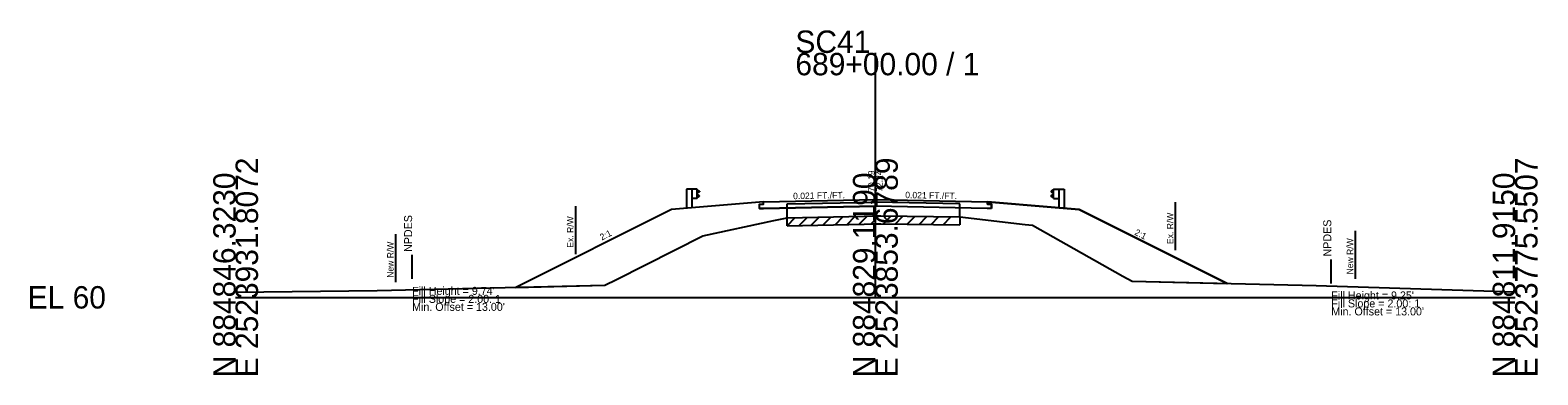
# Model space of a CAD drawing. Extents: x -26 to 183, y -10 to 24021.
# Drawn here: x -25.7 to 162.8, y 16490.3 to 16533.4 of the extents above; entities that cross this region are included whole.
import ezdxf

# ---------------------------------------------------------------- set-up
doc = ezdxf.new("R2010")
doc.units = 0
for name, color, linetype in [('RD_GPK_XS_Cell', 7, 'Continuous'), ('RD_XS_Base', 7, 'Continuous'), ('RD_XS_Buildup', 7, 'Continuous'), ('RD_XS_EarthShd', 7, 'Continuous'), ('RD_XS_EwShp', 7, 'Continuous'), ('RD_XS_ExGround', 7, 'Continuous'), ('RD_XS_ExPaveRet', 7, 'Continuous'), ('RD_XS_ExRW', 7, 'Continuous'), ('RD_XS_GR', 7, 'Continuous'), ('RD_XS_NewRW', 7, 'Continuous'), ('RD_XS_NPDES', 7, 'Continuous'), ('RD_XS_Pave', 7, 'Continuous'), ('RD_XS_TieSlope', 7, 'Continuous'), ('RD_XS_TX_Elev_EX', 7, 'Continuous'), ('RD_XS_TX_Elev_PR', 7, 'Continuous'), ('RD_XS_TX_Slope', 7, 'Continuous'), ('RD_XS_TX_Warning', 7, 'Continuous')]:
    doc.layers.add(name, color=color, linetype=linetype)

msp = doc.modelspace()

# ---------------------------------------------------------------- linework, layer by layer
at = {"layer": 'RD_GPK_XS_Cell'}
for p, q in [((80, 16500), (80, 16530.57)), ((0, 16500), (80, 16500)), ((80, 16500), (160, 16500))]:
    msp.add_line(p, q, dxfattribs=at)
at = {"layer": 'RD_XS_Base'}
for p in [(66.01, 16511.11), (93.99, 16511.11)]:
    msp.add_line(p, (80, 16511.4), dxfattribs=at)
at = {"layer": 'RD_XS_Buildup'}
for p, q in [((68.96, 16511.69), (80, 16511.92)), ((68.96, 16509.94), (68.96, 16511.69)), ((90.58, 16511.7), (80, 16511.92)), ((90.58, 16510.05), (90.58, 16511.7))]:
    msp.add_line(p, q, dxfattribs=at)
at = {"layer": 'RD_XS_EarthShd'}
for p, q in [((66, 16511.95), (58, 16511.28)), ((94, 16511.95), (102, 16511.28)), ((58, 16511.28), (54.5, 16510.99)), ((102, 16511.28), (105.5, 16510.99))]:
    msp.add_line(p, q, dxfattribs=at)
at = {"layer": 'RD_XS_EwShp'}
msp.add_lwpolyline([(94.5, 16511.1), (93.99, 16511.11), (80, 16511.4), (66.01, 16511.11), (65.5, 16511.1), (65.5, 16511.65), (66, 16511.66), (66, 16511.95), (58, 16511.28), (54.5, 16510.99), (35.02, 16501.25), (46.18, 16501.51), (47.64, 16502.25), (58.42, 16507.69), (67.29, 16509.59), (68.96, 16509.94), (78.58, 16510.16), (79.65, 16510.19), (80, 16510.19), (80.67, 16510.18), (90.58, 16510.05), (98.72, 16509.13), (99.65, 16509.01), (110.95, 16502.65), (112.09, 16502.01), (124.01, 16501.74), (105.5, 16510.99), (102, 16511.28), (94, 16511.95), (94, 16511.66), (94.5, 16511.65)], close=True, dxfattribs=at)
msp.add_lwpolyline([(94.5, 16511.1), (93.99, 16511.11), (80, 16511.4), (66.01, 16511.11), (65.5, 16511.1), (65.5, 16511.65), (66, 16511.66), (66, 16511.95), (58, 16511.28), (54.5, 16510.99), (35.02, 16501.25), (46.18, 16501.51), (47.64, 16502.25), (58.42, 16507.69), (67.29, 16509.59), (68.96, 16509.94), (78.58, 16510.16), (79.65, 16510.19), (80, 16510.19), (80.67, 16510.18), (90.58, 16510.05), (98.72, 16509.13), (99.65, 16509.01), (110.95, 16502.65), (112.09, 16502.01), (124.01, 16501.74), (105.5, 16510.99), (102, 16511.28), (94, 16511.95), (94, 16511.66), (94.5, 16511.65)], close=True, dxfattribs=at)
msp.add_lwpolyline([(94.5, 16511.1), (93.99, 16511.11), (80, 16511.4), (66.01, 16511.11), (65.5, 16511.1), (65.5, 16511.65), (66, 16511.66), (66, 16511.95), (58, 16511.28), (54.5, 16510.99), (35.02, 16501.25), (46.18, 16501.51), (47.64, 16502.25), (58.42, 16507.69), (67.29, 16509.59), (68.96, 16509.94), (78.58, 16510.16), (79.65, 16510.19), (80, 16510.19), (80.67, 16510.18), (90.58, 16510.05), (98.72, 16509.13), (99.65, 16509.01), (110.95, 16502.65), (112.09, 16502.01), (124.01, 16501.74), (105.5, 16510.99), (102, 16511.28), (94, 16511.95), (94, 16511.66), (94.5, 16511.65)], close=True, dxfattribs=at)
msp.add_lwpolyline([(94.5, 16511.1), (93.99, 16511.11), (80, 16511.4), (66.01, 16511.11), (65.5, 16511.1), (65.5, 16511.65), (66, 16511.66), (66, 16511.95), (58, 16511.28), (54.5, 16510.99), (35.02, 16501.25), (46.18, 16501.51), (47.64, 16502.25), (58.42, 16507.69), (67.29, 16509.59), (68.96, 16509.94), (78.58, 16510.16), (79.65, 16510.19), (80, 16510.19), (80.67, 16510.18), (90.58, 16510.05), (98.72, 16509.13), (99.65, 16509.01), (110.95, 16502.65), (112.09, 16502.01), (124.01, 16501.74), (105.5, 16510.99), (102, 16511.28), (94, 16511.95), (94, 16511.66), (94.5, 16511.65)], close=True, dxfattribs=at)
at = {"layer": 'RD_XS_ExGround'}
for p, q in [((67.29, 16509.59), (68.96, 16509.94)), ((68.96, 16509.94), (78.58, 16510.16)), ((78.58, 16510.16), (79.65, 16510.19)), ((79.65, 16510.19), (80, 16510.19)), ((80, 16510.19), (80.67, 16510.18)), ((80.67, 16510.18), (90.58, 16510.05)), ((90.58, 16510.05), (98.72, 16509.13)), ((58.42, 16507.69), (67.29, 16509.59)), ((98.72, 16509.13), (99.65, 16509.01)), ((99.65, 16509.01), (110.95, 16502.65)), ((47.64, 16502.25), (58.42, 16507.69)), ((110.95, 16502.65), (112.09, 16502.01)), ((0, 16500.64), (17.69, 16500.85)), ((17.69, 16500.85), (46.18, 16501.51)), ((46.18, 16501.51), (47.64, 16502.25)), ((112.09, 16502.01), (135.13, 16501.48)), ((135.13, 16501.48), (160, 16500.69))]:
    msp.add_line(p, q, dxfattribs=at)
at = {"layer": 'RD_XS_ExPaveRet'}
for p, q in [((68.96, 16508.94), (69.98, 16509.97)), ((68.96, 16508.94), (68.96, 16509.94)), ((70.46, 16508.98), (71.48, 16510)), ((71.96, 16509.01), (72.98, 16510.04)), ((73.46, 16509.05), (74.48, 16510.07)), ((74.96, 16509.08), (75.98, 16510.11)), ((76.46, 16509.12), (77.48, 16510.14)), ((77.96, 16509.15), (78.98, 16510.17)), ((79.46, 16509.19), (80.45, 16510.18)), ((80.96, 16509.17), (81.94, 16510.16)), ((82.46, 16509.16), (83.44, 16510.14)), ((83.96, 16509.14), (84.94, 16510.12)), ((85.46, 16509.12), (86.44, 16510.11)), ((86.96, 16509.1), (87.94, 16510.09)), ((88.46, 16509.08), (89.44, 16510.07)), ((90.58, 16510.05), (90.58, 16509.05)), ((68.96, 16508.94), (78.58, 16509.16)), ((78.58, 16509.16), (79.65, 16509.19)), ((79.65, 16509.19), (80, 16509.19)), ((80, 16509.19), (80.67, 16509.18)), ((80.67, 16509.18), (90.58, 16509.05))]:
    msp.add_line(p, q, dxfattribs=at)
at = {"layer": 'RD_XS_ExRW'}
for p, q in [((117.5, 16511.89), (117.5, 16505.89)), ((42.5, 16511.42), (42.5, 16505.42))]:
    msp.add_line(p, q, dxfattribs=at)
at = {"layer": 'RD_XS_GR'}
for p, q in [((56.4, 16513.53), (56.4, 16511.15)), ((57.06, 16513.53), (56.4, 16513.53)), ((57.06, 16513.53), (57.06, 16511.2)), ((57.73, 16513.53), (57.06, 16513.53)), ((57.73, 16512.36), (57.06, 16512.36)), ((57.73, 16512.36), (57.73, 16513.53)), ((57.73, 16513.46), (58, 16513.26)), ((58, 16513.21), (57.73, 16513.01)), ((58, 16512.69), (57.73, 16512.89)), ((57.73, 16512.44), (58, 16512.64)), ((58, 16513.26), (58, 16513.21)), ((58, 16512.64), (58, 16512.69)), ((102.27, 16513.46), (102, 16513.26)), ((102, 16513.26), (102, 16513.21)), ((102, 16513.21), (102.27, 16513.01)), ((102, 16512.69), (102.27, 16512.89)), ((102, 16512.64), (102, 16512.69)), ((102.27, 16512.44), (102, 16512.64)), ((102.27, 16512.36), (102.27, 16513.53)), ((102.27, 16513.53), (102.94, 16513.53)), ((102.27, 16512.36), (102.94, 16512.36)), ((102.94, 16513.53), (102.94, 16511.2)), ((102.94, 16513.53), (103.6, 16513.53)), ((103.6, 16513.53), (103.6, 16511.15))]:
    msp.add_line(p, q, dxfattribs=at)
at = {"layer": 'RD_XS_NewRW'}
for p, q in [((140, 16508.32), (140, 16502.32)), ((20, 16507.9), (20, 16501.9))]:
    msp.add_line(p, q, dxfattribs=at)
at = {"layer": 'RD_XS_NPDES'}
for p, q in [((22.07, 16502.31), (22.07, 16505.31)), ((137.01, 16501.74), (137.01, 16504.74))]:
    msp.add_line(p, q, dxfattribs=at)
at = {"layer": 'RD_XS_Pave'}
for p, q in [((66, 16511.95), (80, 16512.24)), ((66, 16511.66), (66, 16511.95)), ((80, 16512.24), (94, 16511.95)), ((94, 16511.66), (94, 16511.95)), ((65.5, 16511.65), (66, 16511.66)), ((65.5, 16511.1), (65.5, 16511.65)), ((65.5, 16511.1), (66.01, 16511.11)), ((94.5, 16511.1), (93.99, 16511.11)), ((94.5, 16511.65), (94, 16511.66)), ((94.5, 16511.1), (94.5, 16511.65))]:
    msp.add_line(p, q, dxfattribs=at)
at = {"layer": 'RD_XS_TieSlope'}
for p, q in [((54.5, 16510.99), (35.02, 16501.25)), ((105.5, 16510.99), (124.01, 16501.74))]:
    msp.add_line(p, q, dxfattribs=at)

# ---------------------------------------------------------------- texts
at = {"layer": 'RD_GPK_XS_Cell'}
for s, p in [('SC41', (70, 16530.57)), ('689+00.00 / 1', (70, 16527.77)), ('EL 60', (-26, 16498.6))]:
    msp.add_text(s, height=2.8, dxfattribs=at).set_placement(p)
for s, p in [('N 884846.3230', (0, 16490)), ('E 2523931.8072', (2.8, 16490)), ('N 884829.1190', (80, 16490)), ('E 2523853.6789', (82.8, 16490)), ('N 884811.9150', (160, 16490)), ('E 2523775.5507', (162.8, 16490))]:
    msp.add_text(s, height=2.8, rotation=90, dxfattribs=at).set_placement(p)
at = {"layer": 'RD_XS_ExRW'}
for p in [(42.25, 16506.21), (117.25, 16506.67)]:
    msp.add_text('Ex. R/W ', height=0.8, rotation=90, dxfattribs=at).set_placement(p)
at = {"layer": 'RD_XS_NewRW'}
for p in [(19.75, 16502.45), (139.75, 16502.87)]:
    msp.add_text('New R/W ', height=0.8, rotation=90, dxfattribs=at).set_placement(p)
at = {"layer": 'RD_XS_TX_Elev_EX'}
msp.add_text('70.19', height=0.8, rotation=90, dxfattribs=at).set_placement((79.9, 16513.19))
at = {"layer": 'RD_XS_TX_Elev_PR'}
msp.add_text('72.24', height=0.8, rotation=90, dxfattribs=at).set_placement((80.9, 16513.19))
at = {"layer": 'RD_XS_TX_Slope'}
for s, rotation, p in [('0.021 FT./FT.', 1.1916, (69.72, 16512.27)), ('0.021 FT./FT.', 358.8084, (83.73, 16512.41)), ('2:1', 26.5651, (45.78, 16507.1)), ('2:1', 333.4349, (112.33, 16507.87))]:
    msp.add_text(s, height=0.8, rotation=rotation, dxfattribs=at).set_placement(p)
at = {"layer": 'RD_XS_TX_Warning'}
for p in [(22.07, 16505.31), (137.01, 16504.74)]:
    msp.add_text(' NPDES', height=1, rotation=90, dxfattribs=at).set_placement(p)
for s, p in [("Fill Height = 9.74' ", (22.07, 16500.31)), ("Fill Height = 9.25' ", (137.01, 16499.74)), ('Fill Slope = 2.00: 1', (22.07, 16499.31)), ("Min. Offset = 13.00' ", (22.07, 16498.31)), ('Fill Slope = 2.00: 1', (137.01, 16498.74)), ("Min. Offset = 13.00' ", (137.01, 16497.74))]:
    msp.add_text(s, height=1, dxfattribs=at).set_placement(p)

doc.saveas('drawing.dxf')
